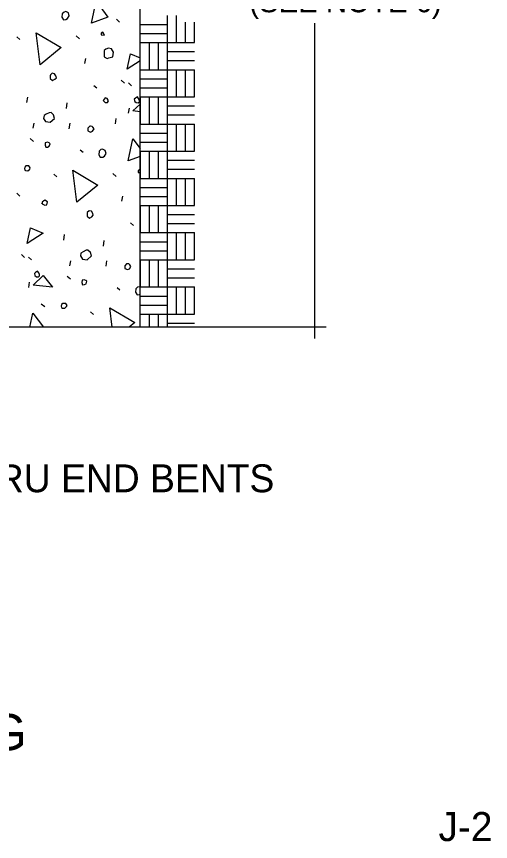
# Model space of a CAD drawing. Extents: x -1660015.2 to -1659984.9, y 2580594.2 to 2580616.7.
# Drawn here: x -1659988.32 to -1659985.06, y 2580594.23 to 2580599.91 of the extents above; entities that cross this region are included whole.
import ezdxf

# ---------------------------------------------------------------- set-up
doc = ezdxf.new("R2010")
doc.units = 0
for name, color, linetype in [('Miscellaneous', 7, 'Continuous'), ('Miscellaneous3', 7, 'Continuous'), ('Miscellaneous4', 7, 'Continuous'), ('PlotBorder_dp', 7, 'Continuous'), ('SheetLines_dp', 7, 'Continuous'), ('TextShtNo', 7, 'Continuous')]:
    doc.layers.add(name, color=color, linetype=linetype)

msp = doc.modelspace()

# ---------------------------------------------------------------- linework, layer by layer
at = {"layer": 'Miscellaneous'}
for p, q in [((-1659987.2832, 2580599.5396), (-1659987.2832, 2580599.9134)), ((-1659987.2219, 2580599.7271), (-1659987.2219, 2580599.9134)), ((-1659987.6339, 2580599.8883), (-1659987.613, 2580599.868)), ((-1659987.4719, 2580599.8509), (-1659987.2832, 2580599.8509)), ((-1659987.1594, 2580599.7272), (-1659987.1594, 2580599.8675)), ((-1659987.0969, 2580599.7272), (-1659987.0969, 2580599.8675)), ((-1659987.4719, 2580599.7884), (-1659987.2832, 2580599.7884)), ((-1659988.3208, 2580599.7663), (-1659988.3005, 2580599.7485)), ((-1659987.9134, 2580599.772), (-1659987.89, 2580599.7524)), ((-1659987.4719, 2580599.7271), (-1659987.0969, 2580599.7271)), ((-1659987.4094, 2580599.7271), (-1659987.4094, 2580599.5396)), ((-1659987.3469, 2580599.7271), (-1659987.3469, 2580599.5396)), ((-1659987.8519, 2580599.5814), (-1659987.8459, 2580599.6167)), ((-1659987.2832, 2580599.6646), (-1659987.0969, 2580599.6646)), ((-1659987.2832, 2580599.6021), (-1659987.0969, 2580599.6021)), ((-1659987.4719, 2580599.5396), (-1659987.2832, 2580599.5396)), ((-1659987.2832, 2580599.1659), (-1659987.2832, 2580599.5396)), ((-1659987.2832, 2580599.5396), (-1659987.0969, 2580599.5396)), ((-1659987.2219, 2580599.3534), (-1659987.2219, 2580599.5396)), ((-1659987.1594, 2580599.3534), (-1659987.1594, 2580599.5396)), ((-1659987.0969, 2580599.3534), (-1659987.0969, 2580599.5396)), ((-1659987.6014, 2580599.4673), (-1659987.5804, 2580599.4471)), ((-1659987.5526, 2580599.4494), (-1659987.5316, 2580599.4291)), ((-1659987.4719, 2580599.4771), (-1659987.2832, 2580599.4771)), ((-1659987.7912, 2580599.432), (-1659987.7709, 2580599.4142)), ((-1659987.4719, 2580599.4146), (-1659987.2832, 2580599.4146)), ((-1659988.2513, 2580599.3139), (-1659988.2459, 2580599.3516)), ((-1659987.4719, 2580599.3534), (-1659987.0969, 2580599.3534)), ((-1659987.4719, 2580599.3534), (-1659987.4719, 2580599.1659)), ((-1659987.4094, 2580599.3534), (-1659987.4094, 2580599.1659)), ((-1659987.3469, 2580599.3534), (-1659987.3469, 2580599.1659)), ((-1659987.9789, 2580599.273), (-1659987.9735, 2580599.3107)), ((-1659987.5509, 2580599.2402), (-1659987.5448, 2580599.2755)), ((-1659987.2832, 2580599.2909), (-1659987.0969, 2580599.2909)), ((-1659987.2832, 2580599.2284), (-1659987.0969, 2580599.2284)), ((-1659988.2089, 2580599.1363), (-1659988.2028, 2580599.1716)), ((-1659987.9596, 2580599.1332), (-1659987.9542, 2580599.1709)), ((-1659987.6424, 2580599.1665), (-1659987.637, 2580599.2042)), ((-1659987.4719, 2580599.1659), (-1659987.2832, 2580599.1659)), ((-1659987.2832, 2580599.1659), (-1659987.0969, 2580599.1659)), ((-1659987.2832, 2580598.7921), (-1659987.2832, 2580599.1659)), ((-1659987.2219, 2580598.9796), (-1659987.2219, 2580599.1659)), ((-1659987.1594, 2580598.9796), (-1659987.1594, 2580599.1659)), ((-1659987.0969, 2580598.9796), (-1659987.0969, 2580599.1659)), ((-1659988.229, 2580599.0663), (-1659988.2056, 2580599.0466)), ((-1659987.4719, 2580599.1034), (-1659987.2832, 2580599.1034)), ((-1659987.4719, 2580599.0409), (-1659987.2832, 2580599.0409)), ((-1659987.8844, 2580598.9878), (-1659987.8647, 2580598.9723)), ((-1659987.4719, 2580598.9796), (-1659987.0969, 2580598.9796)), ((-1659987.4719, 2580598.9796), (-1659987.4719, 2580598.7921)), ((-1659987.4094, 2580598.9796), (-1659987.4094, 2580598.7921)), ((-1659987.3469, 2580598.9796), (-1659987.3469, 2580598.7921)), ((-1659987.2832, 2580598.9171), (-1659987.0969, 2580598.9171)), ((-1659987.6597, 2580598.8254), (-1659987.6363, 2580598.8058)), ((-1659987.2832, 2580598.8546), (-1659987.0969, 2580598.8546)), ((-1659988.0671, 2580598.8197), (-1659988.0468, 2580598.8019)), ((-1659987.4719, 2580598.7921), (-1659987.2832, 2580598.7921)), ((-1659987.2832, 2580598.4184), (-1659987.2832, 2580598.7921)), ((-1659987.2832, 2580598.7921), (-1659987.0969, 2580598.7921)), ((-1659987.2219, 2580598.6059), (-1659987.2219, 2580598.7921)), ((-1659987.1594, 2580598.6059), (-1659987.1594, 2580598.7921)), ((-1659987.0969, 2580598.6059), (-1659987.0969, 2580598.7921)), ((-1659987.4719, 2580598.7296), (-1659987.2832, 2580598.7296)), ((-1659988.3221, 2580598.6893), (-1659988.3011, 2580598.669)), ((-1659987.5983, 2580598.6348), (-1659987.5922, 2580598.6701)), ((-1659987.4719, 2580598.6671), (-1659987.2832, 2580598.6671)), ((-1659987.4719, 2580598.6059), (-1659987.0969, 2580598.6059)), ((-1659987.4719, 2580598.6059), (-1659987.4719, 2580598.4184)), ((-1659987.4094, 2580598.6059), (-1659987.4094, 2580598.4184)), ((-1659987.3469, 2580598.6059), (-1659987.3469, 2580598.4184)), ((-1659987.2832, 2580598.5434), (-1659987.0969, 2580598.5434)), ((-1659987.5376, 2580598.4854), (-1659987.5173, 2580598.4676)), ((-1659987.2832, 2580598.4809), (-1659987.0969, 2580598.4809)), ((-1659987.9977, 2580598.3673), (-1659987.9922, 2580598.405)), ((-1659987.4719, 2580598.4184), (-1659987.2832, 2580598.4184)), ((-1659987.2832, 2580598.4184), (-1659987.0969, 2580598.4184)), ((-1659987.2832, 2580598.0446), (-1659987.2832, 2580598.4184)), ((-1659987.2219, 2580598.2321), (-1659987.2219, 2580598.4184)), ((-1659987.1594, 2580598.2321), (-1659987.1594, 2580598.4184)), ((-1659987.0969, 2580598.2321), (-1659987.0969, 2580598.4184)), ((-1659987.7253, 2580598.3264), (-1659987.7199, 2580598.3641)), ((-1659987.4719, 2580598.3559), (-1659987.2832, 2580598.3559)), ((-1659988.2895, 2580598.2684), (-1659988.2686, 2580598.2481)), ((-1659987.4719, 2580598.2934), (-1659987.2832, 2580598.2934)), ((-1659988.2407, 2580598.2504), (-1659988.2197, 2580598.2301)), ((-1659987.9553, 2580598.1897), (-1659987.9492, 2580598.225)), ((-1659987.706, 2580598.1866), (-1659987.7005, 2580598.2243)), ((-1659987.4719, 2580598.2321), (-1659987.0969, 2580598.2321)), ((-1659987.4719, 2580598.2321), (-1659987.4719, 2580598.0446)), ((-1659987.4094, 2580598.2321), (-1659987.4094, 2580598.0446)), ((-1659987.3469, 2580598.2321), (-1659987.3469, 2580598.0446)), ((-1659987.2832, 2580598.1696), (-1659987.0969, 2580598.1696)), ((-1659987.9753, 2580598.1196), (-1659987.9519, 2580598.1)), ((-1659987.2832, 2580598.1071), (-1659987.0969, 2580598.1071)), ((-1659988.239, 2580598.0412), (-1659988.2329, 2580598.0765)), ((-1659987.6308, 2580598.0411), (-1659987.6111, 2580598.0257)), ((-1659987.4719, 2580598.0446), (-1659987.2832, 2580598.0446)), ((-1659987.2832, 2580597.7672), (-1659987.2832, 2580598.0447)), ((-1659987.2832, 2580598.0446), (-1659987.0969, 2580598.0446)), ((-1659987.2219, 2580597.8584), (-1659987.2219, 2580598.0446)), ((-1659987.1594, 2580597.8584), (-1659987.1594, 2580598.0446)), ((-1659987.0969, 2580597.8584), (-1659987.0969, 2580598.0446)), ((-1659987.4719, 2580597.9821), (-1659987.2832, 2580597.9821)), ((-1659988.1546, 2580597.9292), (-1659988.1289, 2580597.9103)), ((-1659987.4719, 2580597.9196), (-1659987.2832, 2580597.9196)), ((-1659987.8135, 2580597.8731), (-1659987.7932, 2580597.8553)), ((-1659987.4719, 2580597.8584), (-1659987.0969, 2580597.8584)), ((-1659987.4094, 2580597.8584), (-1659987.4094, 2580597.7672)), ((-1659987.3469, 2580597.8584), (-1659987.3469, 2580597.7672)), ((-1659987.2832, 2580597.7959), (-1659987.0969, 2580597.7959))]:
    msp.add_line(p, q, dxfattribs=at)
for points in [[(-1659987.8075, 2580599.8599), (-1659987.7755, 2580600.0108), (-1659987.6942, 2580599.9006), (-1659987.8075, 2580599.8599)], [(-1659988.0087, 2580599.925), (-1659988.0101, 2580599.9013), (-1659988.0001, 2580599.8833), (-1659987.9826, 2580599.8854), (-1659987.9712, 2580599.8911), (-1659987.9605, 2580599.9095), (-1659987.9664, 2580599.9312), (-1659987.9841, 2580599.9394), (-1659987.9962, 2580599.9361), (-1659988.0087, 2580599.925)], [(-1659988.1605, 2580599.5738), (-1659988.1884, 2580599.794), (-1659988.0163, 2580599.6926), (-1659988.1605, 2580599.5738)], [(-1659987.7394, 2580599.7798), (-1659987.7182, 2580599.7777), (-1659987.7208, 2580599.7873), (-1659987.7288, 2580599.7981), (-1659987.7396, 2580599.7901), (-1659987.7394, 2580599.7798)], [(-1659987.7206, 2580599.6709), (-1659987.7193, 2580599.6273), (-1659987.6985, 2580599.6173), (-1659987.6864, 2580599.6206), (-1659987.6599, 2580599.6277), (-1659987.6556, 2580599.6599), (-1659987.6699, 2580599.6845), (-1659987.6888, 2580599.6872), (-1659987.7081, 2580599.682), (-1659987.7206, 2580599.6709)], [(-1659987.562, 2580599.5426), (-1659987.539, 2580599.6497), (-1659987.472, 2580599.622)], [(-1659987.472, 2580599.6005), (-1659987.562, 2580599.5426)], [(-1659988.0907, 2580599.4967), (-1659988.091, 2580599.4785), (-1659988.0744, 2580599.4648), (-1659988.0587, 2580599.4742), (-1659988.0486, 2580599.4847), (-1659988.0518, 2580599.4968), (-1659988.0612, 2580599.5124), (-1659988.0776, 2580599.5157), (-1659988.0902, 2580599.5046), (-1659988.0907, 2580599.4967)], [(-1659987.727, 2580599.3276), (-1659987.7128, 2580599.3133), (-1659987.6977, 2580599.3147), (-1659987.6899, 2580599.3246), (-1659987.6912, 2580599.3294), (-1659987.7, 2580599.3426), (-1659987.7116, 2580599.3472), (-1659987.7193, 2580599.3374), (-1659987.727, 2580599.3276)], [(-1659987.508, 2580599.3216), (-1659987.4981, 2580599.3138), (-1659987.4848, 2580599.3122), (-1659987.4764, 2580599.3197), (-1659987.4766, 2580599.33), (-1659987.4822, 2580599.3414), (-1659987.4903, 2580599.3522), (-1659987.5035, 2580599.3435), (-1659987.5119, 2580599.336), (-1659987.508, 2580599.3216)], [(-1659987.5214, 2580599.2558), (-1659987.472, 2580599.3018)], [(-1659988.1367, 2580599.2049), (-1659988.123, 2580599.1826), (-1659988.0908, 2580599.1783), (-1659988.0615, 2580599.2043), (-1659988.068, 2580599.2285), (-1659988.0852, 2580599.2445), (-1659988.0979, 2580599.2437), (-1659988.1184, 2580599.2331), (-1659988.134, 2580599.2237), (-1659988.1367, 2580599.2049)], [(-1659987.472, 2580599.2508), (-1659987.5214, 2580599.2558)], [(-1659987.8311, 2580599.1366), (-1659987.8314, 2580599.1184), (-1659987.8137, 2580599.1102), (-1659987.7998, 2580599.1165), (-1659987.7886, 2580599.1325), (-1659987.7967, 2580599.1433), (-1659987.8034, 2580599.1492), (-1659987.8144, 2580599.1515), (-1659987.8192, 2580599.1502), (-1659987.8311, 2580599.1366)], [(-1659987.5539, 2580598.9133), (-1659987.5218, 2580599.0642), (-1659987.472, 2580598.9966)], [(-1659988.1263, 2580599.0213), (-1659988.1224, 2580599.0068), (-1659988.1097, 2580599.0076), (-1659988.0983, 2580599.0133), (-1659988.0925, 2580599.0303), (-1659988.0993, 2580599.0363), (-1659988.1109, 2580599.0409), (-1659988.1254, 2580599.0371), (-1659988.1263, 2580599.0213)], [(-1659987.7551, 2580598.9784), (-1659987.7565, 2580598.9547), (-1659987.7465, 2580598.9367), (-1659987.7289, 2580598.9388), (-1659987.7175, 2580598.9445), (-1659987.7069, 2580598.9628), (-1659987.7127, 2580598.9846), (-1659987.7305, 2580598.9928), (-1659987.7425, 2580598.9895), (-1659987.7551, 2580598.9784)], [(-1659987.472, 2580598.9427), (-1659987.5539, 2580598.9133)], [(-1659988.2665, 2580598.8491), (-1659988.2604, 2580598.8456), (-1659988.2446, 2580598.8446), (-1659988.2321, 2580598.8558), (-1659988.2292, 2580598.8643), (-1659988.2379, 2580598.8775), (-1659988.2585, 2580598.8772), (-1659988.2669, 2580598.8697), (-1659988.2691, 2580598.8588), (-1659988.2665, 2580598.8491)], [(-1659987.9068, 2580598.6272), (-1659987.9348, 2580598.8474), (-1659987.7627, 2580598.746), (-1659987.9068, 2580598.6272)], [(-1659987.472, 2580598.8472), (-1659987.4752, 2580598.8515), (-1659987.486, 2580598.8435), (-1659987.4858, 2580598.8332)], [(-1659987.4858, 2580598.8332), (-1659987.472, 2580598.8318)], [(-1659988.1474, 2580598.617), (-1659988.129, 2580598.6064), (-1659988.1146, 2580598.6103), (-1659988.1094, 2580598.6298), (-1659988.1284, 2580598.6428), (-1659988.1368, 2580598.6354), (-1659988.1458, 2580598.6304), (-1659988.1474, 2580598.617), (-1659988.1487, 2580598.6219)], [(-1659987.837, 2580598.5501), (-1659987.8373, 2580598.5319), (-1659987.8207, 2580598.5182), (-1659987.8051, 2580598.5276), (-1659987.795, 2580598.5381), (-1659987.7982, 2580598.5502), (-1659987.8076, 2580598.5658), (-1659987.824, 2580598.5691), (-1659987.8365, 2580598.558), (-1659987.837, 2580598.5501)], [(-1659988.2502, 2580598.3436), (-1659988.2271, 2580598.4508), (-1659988.1398, 2580598.4146), (-1659988.2502, 2580598.3436)], [(-1659987.472, 2580598.3827), (-1659987.4733, 2580598.381)], [(-1659987.4733, 2580598.381), (-1659987.472, 2580598.3796)], [(-1659987.883, 2580598.2582), (-1659987.8693, 2580598.236), (-1659987.8371, 2580598.2317), (-1659987.8078, 2580598.2577), (-1659987.8143, 2580598.2818), (-1659987.8316, 2580598.2979), (-1659987.8443, 2580598.2971), (-1659987.8647, 2580598.2865), (-1659987.8803, 2580598.2771), (-1659987.883, 2580598.2582)], [(-1659987.5775, 2580598.19), (-1659987.5778, 2580598.1718), (-1659987.56, 2580598.1636), (-1659987.5462, 2580598.1699), (-1659987.535, 2580598.1859), (-1659987.543, 2580598.1967), (-1659987.5498, 2580598.2026), (-1659987.5607, 2580598.2048), (-1659987.5656, 2580598.2036), (-1659987.5775, 2580598.19)], [(-1659988.1961, 2580598.1226), (-1659988.1863, 2580598.1149), (-1659988.1729, 2580598.1133), (-1659988.1645, 2580598.1207), (-1659988.1647, 2580598.131), (-1659988.1704, 2580598.1424), (-1659988.1784, 2580598.1532), (-1659988.1916, 2580598.1445), (-1659988.2, 2580598.1371), (-1659988.1961, 2580598.1226)], [(-1659988.2096, 2580598.0569), (-1659988.1391, 2580598.1223), (-1659988.0765, 2580598.0434), (-1659988.2096, 2580598.0569)], [(-1659987.8727, 2580598.0747), (-1659987.8688, 2580598.0602), (-1659987.8561, 2580598.061), (-1659987.8446, 2580598.0667), (-1659987.8389, 2580598.0837), (-1659987.8456, 2580598.0897), (-1659987.8572, 2580598.0943), (-1659987.8717, 2580598.0905), (-1659987.8727, 2580598.0747)], [(-1659987.5014, 2580598.0318), (-1659987.5029, 2580598.0081), (-1659987.4928, 2580597.9901), (-1659987.4753, 2580597.9922), (-1659987.472, 2580597.9939)], [(-1659987.472, 2580598.0439), (-1659987.4768, 2580598.0462), (-1659987.4889, 2580598.0429), (-1659987.5014, 2580598.0318)], [(-1659988.0129, 2580597.9025), (-1659988.0068, 2580597.899), (-1659987.991, 2580597.898), (-1659987.9784, 2580597.9092), (-1659987.9756, 2580597.9177), (-1659987.9843, 2580597.9309), (-1659988.0049, 2580597.9305), (-1659988.0132, 2580597.9231), (-1659988.0155, 2580597.9122), (-1659988.0129, 2580597.9025)], [(-1659988.2308, 2580597.7673), (-1659988.21, 2580597.8652), (-1659988.1377, 2580597.7673)], [(-1659987.6642, 2580597.7673), (-1659987.6812, 2580597.9008), (-1659987.509, 2580597.7994), (-1659987.548, 2580597.7673)]]:
    msp.add_lwpolyline(points, dxfattribs=at)
at = {"layer": 'Miscellaneous3'}
msp.add_line((-1659987.472, 2580597.7672), (-1659987.472, 2580602.2354), dxfattribs=at)
at = {"layer": 'SheetLines_dp'}
for points in [[(-1659986.2685, 2580597.6897), (-1659986.2685, 2580599.8593)], [(-1659986.1909, 2580597.7671), (-1659989.4814, 2580597.7671), (-1659989.4814, 2580597.8446), (-1659989.5152, 2580597.7671), (-1659989.5489, 2580597.6896), (-1659989.5489, 2580597.7671), (-1659992.7319, 2580597.7671)]]:
    msp.add_lwpolyline(points, dxfattribs=at)

# ---------------------------------------------------------------- texts
at = {"layer": 'Miscellaneous4'}
msp.add_text('MAINTENANCE LIGHTING', height=0.25001, rotation=360, dxfattribs=at).set_placement((-1659992.3581, 2580594.8559))
at = {"layer": 'PlotBorder_dp'}
msp.add_text('STEEL BOX GIRDER BRIDGE SECTION THRU END BENTS', height=0.192, dxfattribs=at).set_placement((-1659993.6377, 2580596.6316))
at = {"layer": 'SheetLines_dp'}
msp.add_text('(SEE NOTE 6)', height=0.1512, dxfattribs=at).set_placement((-1659986.7203, 2580599.935))
at = {"layer": 'TextShtNo'}
msp.add_text('J-2', height=0.2, dxfattribs=at).set_placement((-1659985.4165, 2580594.2309))

doc.saveas('drawing.dxf')
